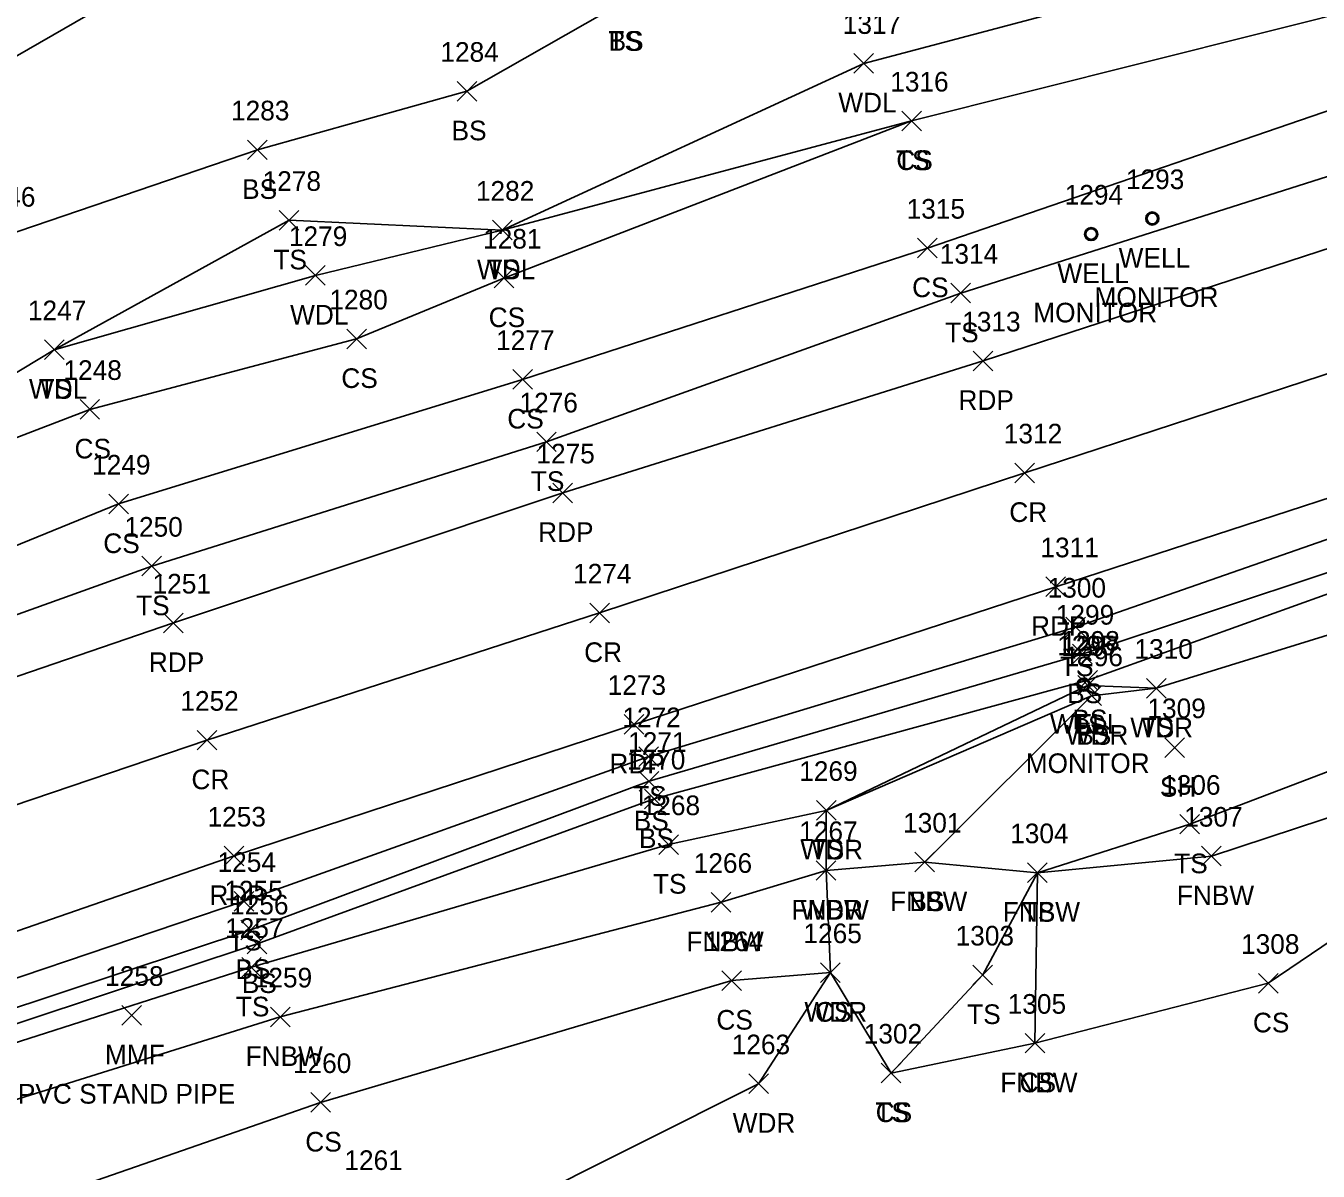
# Model space of a CAD drawing. Extents: x 1443064 to 1445163, y 544063 to 544655.
# Drawn here: x 1443463.7 to 1443595.4, y 544191.5 to 544308.2 of the extents above; entities that cross this region are included whole.
import ezdxf

# ---------------------------------------------------------------- set-up
doc = ezdxf.new("R2010")
doc.units = 0
for name, color, linetype in [('L_A', 7, 'Continuous'), ('L_C', 7, 'Continuous'), ('L_I', 7, 'Continuous'), ('L_TIC', 7, 'Continuous'), ('LAWA', 7, 'Continuous'), ('LELB', 7, 'Continuous'), ('LFNC', 7, 'Continuous'), ('P_A', 7, 'Continuous'), ('P_I', 7, 'Continuous'), ('P_TIC', 7, 'Continuous'), ('PET', 7, 'Continuous'), ('PRC', 7, 'Continuous'), ('U_A', 7, 'Continuous'), ('U_C', 7, 'Continuous'), ('U_I', 7, 'Continuous'), ('UWW', 7, 'Continuous')]:
    doc.layers.add(name, color=color, linetype=linetype)

msp = doc.modelspace()

# ---------------------------------------------------------------- linework, layer by layer
at = {"layer": 'L_TIC'}
for points in [[(1443548.07, 544303.36), (1443550.07, 544305.36)], [(1443550.07, 544303.36), (1443548.07, 544305.36)], [(1443507.64, 544300.52), (1443509.64, 544302.52)], [(1443509.64, 544300.52), (1443507.64, 544302.52)], [(1443552.95, 544297.49), (1443554.95, 544299.49)], [(1443554.95, 544297.49), (1443552.95, 544299.49)], [(1443552.95, 544297.49), (1443554.95, 544299.49)], [(1443554.95, 544297.49), (1443552.95, 544299.49)], [(1443486.3, 544294.55), (1443488.3, 544296.55)], [(1443488.3, 544294.55), (1443486.3, 544296.55)], [(1443489.52, 544287.37), (1443491.52, 544289.37)], [(1443491.52, 544287.37), (1443489.52, 544289.37)], [(1443511.25, 544286.37), (1443513.25, 544288.37)], [(1443513.25, 544286.37), (1443511.25, 544288.37)], [(1443511.25, 544286.37), (1443513.25, 544288.37)], [(1443513.25, 544286.37), (1443511.25, 544288.37)], [(1443554.56, 544284.54), (1443556.56, 544286.54)], [(1443556.56, 544284.54), (1443554.56, 544286.54)], [(1443492.21, 544281.75), (1443494.21, 544283.75)], [(1443494.21, 544281.75), (1443492.21, 544283.75)], [(1443511.42, 544281.49), (1443513.42, 544283.49)], [(1443513.42, 544281.49), (1443511.42, 544283.49)], [(1443557.95, 544279.95), (1443559.95, 544281.95)], [(1443559.95, 544279.95), (1443557.95, 544281.95)], [(1443465.61, 544274.19), (1443467.61, 544276.19)], [(1443467.61, 544274.19), (1443465.61, 544276.19)], [(1443465.61, 544274.19), (1443467.61, 544276.19)], [(1443467.61, 544274.19), (1443465.61, 544276.19)], [(1443496.41, 544275.29), (1443498.41, 544277.29)], [(1443498.41, 544275.29), (1443496.41, 544277.29)], [(1443513.32, 544271.16), (1443515.32, 544273.16)], [(1443515.32, 544271.16), (1443513.32, 544273.16)], [(1443469.23, 544268.11), (1443471.23, 544270.11)], [(1443471.23, 544268.11), (1443469.23, 544270.11)], [(1443515.75, 544264.8), (1443517.75, 544266.8)], [(1443517.75, 544264.8), (1443515.75, 544266.8)], [(1443472.16, 544258.47), (1443474.16, 544260.47)], [(1443474.16, 544258.47), (1443472.16, 544260.47)], [(1443475.53, 544252.14), (1443477.53, 544254.14)], [(1443477.53, 544252.14), (1443475.53, 544254.14)], [(1443569.65, 544245.93), (1443571.65, 544247.93)], [(1443571.65, 544245.93), (1443569.65, 544247.93)], [(1443570.34, 544243.18), (1443572.34, 544245.18)], [(1443572.34, 544243.18), (1443570.34, 544245.18)], [(1443570.88, 544239.98), (1443572.88, 544241.98)], [(1443572.88, 544239.98), (1443570.88, 544241.98)], [(1443570.89, 544240.52), (1443572.89, 544242.52)], [(1443572.89, 544240.52), (1443570.89, 544242.52)], [(1443571.28, 544238.94), (1443573.28, 544240.94)], [(1443573.28, 544238.94), (1443571.28, 544240.94)], [(1443571.28, 544238.94), (1443573.28, 544240.94)], [(1443573.28, 544238.94), (1443571.28, 544240.94)], [(1443577.87, 544239.7), (1443579.87, 544241.7)], [(1443579.87, 544239.7), (1443577.87, 544241.7)], [(1443577.87, 544239.7), (1443579.87, 544241.7)], [(1443579.87, 544239.7), (1443577.87, 544241.7)], [(1443579.75, 544233.65), (1443581.75, 544235.65)], [(1443581.75, 544233.65), (1443579.75, 544235.65)], [(1443526.17, 544232.73), (1443528.17, 544234.73)], [(1443528.17, 544232.73), (1443526.17, 544234.73)], [(1443526.2, 544230.22), (1443528.2, 544232.22)], [(1443528.2, 544230.22), (1443526.2, 544232.22)], [(1443526.73, 544228.42), (1443528.73, 544230.42)], [(1443528.73, 544228.42), (1443526.73, 544230.42)], [(1443544.25, 544227.26), (1443546.25, 544229.26)], [(1443546.25, 544227.26), (1443544.25, 544229.26)], [(1443544.25, 544227.26), (1443546.25, 544229.26)], [(1443546.25, 544227.26), (1443544.25, 544229.26)], [(1443581.29, 544225.85), (1443583.29, 544227.85)], [(1443583.29, 544225.85), (1443581.29, 544227.85)], [(1443528.19, 544223.77), (1443530.19, 544225.77)], [(1443530.19, 544223.77), (1443528.19, 544225.77)], [(1443554.28, 544221.99), (1443556.28, 544223.99)], [(1443556.28, 544221.99), (1443554.28, 544223.99)], [(1443554.28, 544221.99), (1443556.28, 544223.99)], [(1443556.28, 544221.99), (1443554.28, 544223.99)], [(1443583.49, 544222.6), (1443585.49, 544224.6)], [(1443585.49, 544222.6), (1443583.49, 544224.6)], [(1443544.24, 544221.13), (1443546.24, 544223.13)], [(1443546.24, 544221.13), (1443544.24, 544223.13)], [(1443544.24, 544221.13), (1443546.24, 544223.13)], [(1443546.24, 544221.13), (1443544.24, 544223.13)], [(1443565.76, 544220.91), (1443567.76, 544222.91)], [(1443567.76, 544220.91), (1443565.76, 544222.91)], [(1443565.76, 544220.91), (1443567.76, 544222.91)], [(1443567.76, 544220.91), (1443565.76, 544222.91)], [(1443565.76, 544220.91), (1443567.76, 544222.91)], [(1443567.76, 544220.91), (1443565.76, 544222.91)], [(1443484.93, 544217.99), (1443486.93, 544219.99)], [(1443486.93, 544217.99), (1443484.93, 544219.99)], [(1443533.54, 544217.89), (1443535.54, 544219.89)], [(1443535.54, 544217.89), (1443533.54, 544219.89)], [(1443485.62, 544215.08), (1443487.62, 544217.08)], [(1443487.62, 544215.08), (1443485.62, 544217.08)], [(1443486.26, 544213.65), (1443488.26, 544215.65)], [(1443488.26, 544213.65), (1443486.26, 544215.65)], [(1443485.7, 544211.27), (1443487.7, 544213.27)], [(1443487.7, 544211.27), (1443485.7, 544213.27)], [(1443534.62, 544209.92), (1443536.62, 544211.92)], [(1443536.62, 544209.92), (1443534.62, 544211.92)], [(1443544.67, 544210.73), (1443546.67, 544212.73)], [(1443546.67, 544210.73), (1443544.67, 544212.73)], [(1443544.67, 544210.73), (1443546.67, 544212.73)], [(1443546.67, 544210.73), (1443544.67, 544212.73)], [(1443560.2, 544210.49), (1443562.2, 544212.49)], [(1443562.2, 544210.49), (1443560.2, 544212.49)], [(1443589.28, 544209.64), (1443591.28, 544211.64)], [(1443591.28, 544209.64), (1443589.28, 544211.64)], [(1443473.49, 544206.38), (1443475.49, 544208.38)], [(1443475.49, 544206.38), (1443473.49, 544208.38)], [(1443488.63, 544206.22), (1443490.63, 544208.22)], [(1443490.63, 544206.22), (1443488.63, 544208.22)], [(1443565.51, 544203.54), (1443567.51, 544205.54)], [(1443567.51, 544203.54), (1443565.51, 544205.54)], [(1443565.51, 544203.54), (1443567.51, 544205.54)], [(1443567.51, 544203.54), (1443565.51, 544205.54)], [(1443550.85, 544200.5), (1443552.85, 544202.5)], [(1443552.85, 544200.5), (1443550.85, 544202.5)], [(1443550.85, 544200.5), (1443552.85, 544202.5)], [(1443552.85, 544200.5), (1443550.85, 544202.5)], [(1443537.36, 544199.41), (1443539.36, 544201.41)], [(1443539.36, 544199.41), (1443537.36, 544201.41)], [(1443492.74, 544197.5), (1443494.74, 544199.5)], [(1443494.74, 544197.5), (1443492.74, 544199.5)]]:
    msp.add_lwpolyline(points, dxfattribs=at)
at = {"layer": 'LAWA'}
for points in [[(1443161.29, 544157.23), (1443186.09, 544163.69), (1443194.34, 544166.63), (1443196.33, 544167.63), (1443201.36, 544168), (1443240.97, 544179.17), (1443262.42, 544188.86), (1443303.08, 544207.19), (1443347.02, 544222.79), (1443391.79, 544240.14), (1443432.68, 544254.71), (1443466.61, 544275.19), (1443493.21, 544282.75), (1443512.25, 544287.37), (1443549.07, 544304.36), (1443598.9, 544317.54), (1443643.36, 544329.59), (1443677.18, 544341.83), (1443688.03, 544341.71), (1443709.45, 544338.47), (1443741.32, 544354.61), (1443794.32, 544372.46), (1443818.98, 544380.86)], [(1443500.75, 544181.56), (1443538.36, 544200.41), (1443545.67, 544211.73), (1443545.24, 544222.13), (1443545.25, 544228.26), (1443572.28, 544239.94), (1443578.87, 544240.7), (1443627.04, 544255.63), (1443659.19, 544265.88), (1443688.01, 544274.03), (1443699.53, 544278.63), (1443728.36, 544290.25)]]:
    msp.add_lwpolyline(points, dxfattribs=at)
at = {"layer": 'LELB'}
for points in [[(1443073.59, 544128.34), (1443116.66, 544141.89), (1443162.8, 544149.75), (1443198.07, 544157.24), (1443242.5, 544173.41), (1443262.84, 544182.05), (1443307.11, 544199.46), (1443348.85, 544214.35), (1443394.74, 544233.02), (1443435.02, 544243.93), (1443473.16, 544259.47), (1443514.32, 544272.16), (1443555.56, 544285.54), (1443605.06, 544302.52), (1443644.56, 544313.72), (1443676.09, 544324.26), (1443689.45, 544326.75), (1443708.55, 544330.01), (1443714.07, 544333.45), (1443742.84, 544349.83), (1443793.92, 544368.99), (1443822.61, 544377.56)], [(1443074.67, 544122.4), (1443120.32, 544131.74), (1443165.11, 544143.77), (1443199.58, 544153.13), (1443245.24, 544167.88), (1443264.59, 544177.57), (1443308.86, 544194.48), (1443350.56, 544209.36), (1443397.32, 544225.82), (1443437.1, 544238.98), (1443476.53, 544253.14), (1443516.75, 544265.8), (1443558.95, 544280.95), (1443607.52, 544296.39), (1443646.45, 544306.32), (1443685.12, 544319.06), (1443714.26, 544329.16), (1443721.31, 544331.26), (1443744.28, 544345.57), (1443795.65, 544366.53), (1443822.61, 544377.56)], [(1443298.3, 544219.12), (1443343.36, 544234.64), (1443347.13, 544235.69), (1443361.65, 544240.04), (1443373.89, 544246.37), (1443387.28, 544254.4), (1443426.15, 544267.88), (1443461.49, 544286.76), (1443487.3, 544295.55), (1443508.64, 544301.52), (1443524.64, 544310.64), (1443543.83, 544318.46), (1443565.18, 544320.82), (1443579.86, 544324.28), (1443590.71, 544328.22), (1443606.37, 544329.69), (1443641.44, 544343.33), (1443674.4, 544354.73), (1443679.77, 544354.99), (1443682.99, 544355.5), (1443689.34, 544351.28), (1443707.83, 544344.95), (1443741.32, 544354.61)], [(1443361.65, 544240.04), (1443365.6, 544252.15), (1443382.87, 544266.28), (1443423.93, 544281.08), (1443455.64, 544301.02), (1443483.09, 544316.84), (1443502.95, 544323.75), (1443492.91, 544341.29), (1443492.61, 544354.67)], [(1443082.68, 544086.51), (1443130.13, 544099.67), (1443144.13, 544104.98), (1443172.72, 544113.76), (1443212.83, 544125.42), (1443253.97, 544138.87), (1443319.39, 544160.76), (1443361, 544176.06), (1443409.52, 544193.8), (1443447.54, 544206.03), (1443485.93, 544218.99), (1443527.17, 544233.73), (1443570.65, 544246.93), (1443621.44, 544264.66), (1443656.15, 544276.08), (1443695.78, 544288.38), (1443720.36, 544296.79), (1443749.28, 544306.83), (1443759.63, 544310.57), (1443806.78, 544328.14), (1443835.8, 544338.24)], [(1443466.61, 544275.19), (1443490.52, 544288.37), (1443512.25, 544287.37), (1443553.95, 544298.49), (1443601.6, 544310.47), (1443642.31, 544323.29), (1443675.99, 544336.7), (1443688, 544336.24), (1443698.55, 544337.96), (1443699.43, 544334.12), (1443708.55, 544330.01)], [(1443319.92, 544153.98), (1443361.38, 544174.3), (1443410.41, 544191.66), (1443447.48, 544203.1), (1443486.62, 544216.08), (1443527.2, 544231.22), (1443571.34, 544244.18), (1443622.82, 544261.27), (1443656.98, 544272.97), (1443695.69, 544285.56), (1443722.38, 544294.2), (1443748.12, 544301.75), (1443761.69, 544309.21), (1443807.82, 544325.32), (1443837.04, 544335.82)], [(1443432.68, 544254.71), (1443470.23, 544269.11), (1443497.41, 544276.29), (1443512.42, 544282.49), (1443553.95, 544298.49)], [(1443347.34, 544164.94), (1443362.1, 544171.53), (1443410.79, 544190.32), (1443447.84, 544201.59), (1443487.26, 544214.65), (1443527.73, 544229.42), (1443571.89, 544241.52), (1443623.27, 544260), (1443657.62, 544270.44), (1443688.01, 544274.03), (1443701.05, 544275.03), (1443736.1, 544284.41), (1443746.14, 544291.27)], [(1443551.85, 544201.5), (1443561.2, 544211.49), (1443566.76, 544221.91), (1443582.29, 544226.85), (1443631, 544245.39), (1443663.73, 544256.35), (1443704.83, 544270.63), (1443733.57, 544280.99), (1443742.56, 544273.31)], [(1443347.34, 544164.94), (1443362.66, 544168.7), (1443411.3, 544188.87), (1443447.45, 544199.71), (1443486.7, 544212.27), (1443529.19, 544224.77), (1443545.25, 544228.26), (1443571.88, 544240.98), (1443578.87, 544240.7)], [(1443326.71, 544136.88), (1443356.07, 544155.13), (1443385.8, 544161.03), (1443414.14, 544171.77), (1443454.43, 544184.84), (1443493.74, 544198.5), (1443535.62, 544210.92), (1443545.67, 544211.73), (1443551.85, 544201.5), (1443566.51, 544204.54), (1443590.28, 544210.64), (1443632.95, 544239.56)], [(1443572.28, 544239.94), (1443555.28, 544222.99)]]:
    msp.add_lwpolyline(points, dxfattribs=at)
at = {"layer": 'LFNC'}
for points in [[(1443239.88, 544119.45), (1443278.62, 544130.94), (1443320.57, 544148.06), (1443338.13, 544157.08), (1443351.22, 544161.82), (1443363.5, 544166.21), (1443412.24, 544182.91), (1443449.91, 544194.79), (1443489.63, 544207.22), (1443534.54, 544218.89), (1443545.24, 544222.13), (1443555.28, 544222.99), (1443566.76, 544221.91), (1443584.49, 544223.6), (1443632.95, 544239.56), (1443668.35, 544248.03), (1443707.08, 544263.81), (1443742.56, 544273.31)], [(1443566.76, 544221.91), (1443566.51, 544204.54)]]:
    msp.add_lwpolyline(points, dxfattribs=at)
at = {"layer": 'P_TIC'}
for points in [[(1443560.23, 544273.05), (1443562.23, 544275.05)], [(1443562.23, 544273.05), (1443560.23, 544275.05)], [(1443564.47, 544261.64), (1443566.47, 544263.64)], [(1443566.47, 544261.64), (1443564.47, 544263.64)], [(1443517.41, 544259.6), (1443519.41, 544261.6)], [(1443519.41, 544259.6), (1443517.41, 544261.6)], [(1443567.63, 544250.04), (1443569.63, 544252.04)], [(1443569.63, 544250.04), (1443567.63, 544252.04)], [(1443521.16, 544247.37), (1443523.16, 544249.37)], [(1443523.16, 544247.37), (1443521.16, 544249.37)], [(1443477.75, 544246.35), (1443479.75, 544248.35)], [(1443479.75, 544246.35), (1443477.75, 544248.35)], [(1443524.67, 544236.02), (1443526.67, 544238.02)], [(1443526.67, 544236.02), (1443524.67, 544238.02)], [(1443481.15, 544234.41), (1443483.15, 544236.41)], [(1443483.15, 544234.41), (1443481.15, 544236.41)], [(1443483.92, 544222.61), (1443485.92, 544224.61)], [(1443485.92, 544222.61), (1443483.92, 544224.61)]]:
    msp.add_lwpolyline(points, dxfattribs=at)
at = {"layer": 'PET'}
for points in [[(1443075.39, 544117.71), (1443121.41, 544129.24), (1443165.99, 544140.07), (1443200.71, 544149.88), (1443246.42, 544165.39), (1443265.96, 544172.48), (1443311.2, 544187.88), (1443352.92, 544202.76), (1443399.28, 544220.13), (1443438.78, 544233.67), (1443478.75, 544247.35), (1443518.41, 544260.6), (1443561.23, 544274.05), (1443611.7, 544290.5), (1443646.84, 544301.68), (1443684.98, 544314.55), (1443724.57, 544327.54), (1443735.41, 544331.22), (1443748.81, 544336.36), (1443799.43, 544353.96), (1443827.31, 544364.14)], [(1443081.93, 544089.54), (1443128.67, 544104.01), (1443173.03, 544117.15), (1443209.23, 544128.71), (1443253.49, 544142.88), (1443273.3, 544149.07), (1443318.27, 544165.2), (1443359.78, 544179.84), (1443408.54, 544196.96), (1443445.92, 544210.12), (1443484.92, 544223.61), (1443525.67, 544237.02), (1443568.63, 544251.04), (1443620.57, 544267.93), (1443654.52, 544278.93), (1443694.69, 544292.43), (1443717.24, 544299.44), (1443752.8, 544310.97), (1443757.72, 544314.31), (1443805.74, 544330.07), (1443835.35, 544341.18)]]:
    msp.add_lwpolyline(points, dxfattribs=at)
at = {"layer": 'PRC'}
msp.add_lwpolyline([(1443078.47, 544103.68), (1443125.02, 544115.93), (1443169.41, 544128.22), (1443204.47, 544139.4), (1443250.36, 544154.3), (1443269.99, 544160.83), (1443315.13, 544176.71), (1443356.58, 544191.19), (1443403.59, 544208.05), (1443442.67, 544222.02), (1443482.15, 544235.41), (1443522.16, 544248.37), (1443565.47, 544262.64), (1443616.51, 544279.34), (1443650.9, 544289.93), (1443689.58, 544302.53), (1443728.44, 544315.77), (1443753.53, 544324.68), (1443803.56, 544342.2), (1443830.96, 544352.16)], dxfattribs=at)
at = {"layer": 'UWW'}
for centre, radius in [((1443578.47, 544288.55), 0.667), ((1443578.47, 544288.55), 0.625), ((1443578.47, 544288.55), 0.583), ((1443578.47, 544288.55), 0.542), ((1443572.24, 544286.97), 0.667), ((1443572.24, 544286.97), 0.625), ((1443572.24, 544286.97), 0.583), ((1443572.24, 544286.97), 0.542), ((1443571.47, 544241.06), 0.667), ((1443571.47, 544241.06), 0.625), ((1443571.47, 544241.06), 0.583), ((1443571.47, 544241.06), 0.542)]:
    msp.add_circle(centre, radius, dxfattribs=at)

# ---------------------------------------------------------------- texts
at = {"layer": 'L_A'}
for s, p in [('TS', (1443523.05, 544305.64)), ('BS', (1443523.08, 544305.64)), ('BS', (1443523.08, 544305.64)), ('WDL', (1443546.48, 544299.36)), ('BS', (1443507.08, 544296.52)), ('TS', (1443552.36, 544293.49)), ('CS', (1443552.39, 544293.49)), ('BS', (1443485.74, 544290.55)), ('TS', (1443488.93, 544283.37)), ('WDL', (1443509.67, 544282.37)), ('TS', (1443510.66, 544282.37)), ('CS', (1443554, 544280.54)), ('WDL', (1443490.63, 544277.75)), ('CS', (1443510.86, 544277.49)), ('TS', (1443557.36, 544275.95)), ('WDL', (1443464.03, 544270.19)), ('TS', (1443465.02, 544270.19)), ('CS', (1443495.85, 544271.29)), ('CS', (1443512.76, 544267.16)), ('CS', (1443468.67, 544264.11)), ('TS', (1443515.16, 544260.8)), ('CS', (1443471.6, 544254.47)), ('TS', (1443474.94, 544248.14)), ('TS', (1443569.06, 544241.93)), ('BS', (1443569.79, 544239.18)), ('TS', (1443570.29, 544235.98)), ('BS', (1443570.33, 544236.52)), ('WDR', (1443569.64, 544234.94)), ('BS', (1443570.72, 544234.94)), ('WDR', (1443576.23, 544235.7)), ('TS', (1443577.28, 544235.7)), ('SH', (1443579.24, 544229.65)), ('TS', (1443525.58, 544228.73)), ('BS', (1443525.64, 544226.22)), ('BS', (1443526.17, 544224.42)), ('WDR', (1443542.61, 544223.26)), ('TS', (1443543.66, 544223.26)), ('TS', (1443580.7, 544221.85)), ('TS', (1443527.6, 544219.77)), ('FNBW', (1443551.75, 544217.99)), ('BS', (1443553.72, 544217.99)), ('FNBW', (1443580.97, 544218.6)), ('FNBW', (1443541.71, 544217.13)), ('WDR', (1443542.6, 544217.13)), ('FNBW', (1443563.23, 544216.91)), ('FNBW', (1443563.23, 544216.91)), ('TS', (1443565.17, 544216.91)), ('TS', (1443484.34, 544213.99)), ('FNBW', (1443531.01, 544213.89)), ('BS', (1443485.06, 544211.08)), ('BS', (1443485.71, 544209.65)), ('TS', (1443485.11, 544207.27)), ('CS', (1443534.06, 544205.92)), ('WDR', (1443543.03, 544206.73)), ('CS', (1443544.11, 544206.73)), ('TS', (1443559.61, 544206.49)), ('CS', (1443588.72, 544205.64)), ('MMF', (1443471.77, 544202.38)), ('FNBW', (1443486.1, 544202.22)), ('FNBW', (1443562.98, 544199.54)), ('CS', (1443564.95, 544199.54)), ('TS', (1443550.26, 544196.5)), ('CS', (1443550.29, 544196.5)), ('WDR', (1443535.72, 544195.41)), ('CS', (1443492.18, 544193.5))]:
    msp.add_text(s, height=2, dxfattribs=at).set_placement(p)
at = {"layer": 'L_C'}
msp.add_text(' 2"PVC STAND PIPE', height=2, dxfattribs=at).set_placement((1443459.72, 544198.38))
at = {"layer": 'L_I'}
for s, p in [('1317', (1443546.94, 544307.36)), ('1284', (1443505.94, 544304.52)), ('1316', (1443551.77, 544301.49)), ('1316', (1443551.77, 544301.49)), ('1283', (1443484.61, 544298.55)), ('1278', (1443487.83, 544291.37)), ('1282', (1443509.56, 544290.37)), ('1282', (1443509.56, 544290.37)), ('1246', (1443458.74, 544289.76)), ('1315', (1443553.44, 544288.54)), ('1279', (1443490.51, 544285.75)), ('1281', (1443510.29, 544285.49)), ('1314', (1443556.82, 544283.95)), ('1247', (1443463.92, 544278.19)), ('1247', (1443463.92, 544278.19)), ('1280', (1443494.63, 544279.29)), ('1277', (1443511.62, 544275.16)), ('1248', (1443467.54, 544272.11)), ('1276', (1443514, 544268.8)), ('1249', (1443470.46, 544262.47)), ('1250', (1443473.75, 544256.14)), ('1300', (1443567.8, 544249.93)), ('1299', (1443568.64, 544247.18)), ('1297', (1443569.19, 544243.98)), ('1298', (1443569.2, 544244.52)), ('1296', (1443569.53, 544242.94)), ('1296', (1443569.53, 544242.94)), ('1310', (1443576.65, 544243.7)), ('1310', (1443576.65, 544243.7)), ('1309', (1443577.97, 544237.65)), ('1272', (1443524.48, 544236.73)), ('1271', (1443525.07, 544234.22)), ('1270', (1443524.95, 544232.42)), ('1269', (1443542.5, 544231.26)), ('1269', (1443542.5, 544231.26)), ('1306', (1443579.47, 544229.85)), ('1268', (1443526.45, 544227.77)), ('1301', (1443553.08, 544225.99)), ('1301', (1443553.08, 544225.99)), ('1307', (1443581.72, 544226.6)), ('1267', (1443542.5, 544225.13)), ('1267', (1443542.5, 544225.13)), ('1304', (1443563.99, 544224.91)), ('1304', (1443563.99, 544224.91)), ('1304', (1443563.99, 544224.91)), ('1254', (1443483.24, 544221.99)), ('1266', (1443531.75, 544221.89)), ('1255', (1443483.93, 544219.08)), ('1256', (1443484.52, 544217.65)), ('1257', (1443484.01, 544215.27)), ('1264', (1443532.88, 544213.92)), ('1265', (1443542.93, 544214.73)), ('1265', (1443542.93, 544214.73)), ('1303', (1443558.43, 544214.49)), ('1308', (1443587.51, 544213.64)), ('1258', (1443471.79, 544210.38)), ('1259', (1443486.93, 544210.22)), ('1305', (1443563.74, 544207.54)), ('1305', (1443563.74, 544207.54)), ('1302', (1443549.07, 544204.5)), ('1302', (1443549.07, 544204.5)), ('1263', (1443535.62, 544203.41)), ('1260', (1443490.92, 544201.5)), ('1261', (1443496.16, 544191.62))]:
    msp.add_text(s, height=2, dxfattribs=at).set_placement(p)
at = {"layer": 'P_A'}
for s, p in [('RDP', (1443558.72, 544269.05)), ('CR', (1443563.9, 544257.64)), ('RDP', (1443515.9, 544255.6)), ('RDP', (1443566.12, 544246.04)), ('CR', (1443520.59, 544243.37)), ('RDP', (1443476.24, 544242.35)), ('RDP', (1443523.16, 544232.02)), ('CR', (1443480.58, 544230.41)), ('RDP', (1443482.41, 544218.61))]:
    msp.add_text(s, height=2, dxfattribs=at).set_placement(p)
at = {"layer": 'P_I'}
for s, p in [('1313', (1443559.1, 544277.05)), ('1312', (1443563.34, 544265.64)), ('1275', (1443515.72, 544263.6)), ('1311', (1443567.07, 544254.04)), ('1274', (1443519.46, 544251.37)), ('1251', (1443476.62, 544250.35)), ('1273', (1443522.98, 544240.02)), ('1252', (1443479.45, 544238.41)), ('1253', (1443482.22, 544226.61))]:
    msp.add_text(s, height=2, dxfattribs=at).set_placement(p)
at = {"layer": 'U_A'}
for p in [(1443575.04, 544283.55), (1443568.8, 544281.97), (1443568.04, 544236.06)]:
    msp.add_text('WELL', height=2, dxfattribs=at).set_placement(p)
at = {"layer": 'U_C'}
for p in [(1443572.58, 544279.55), (1443566.34, 544277.97), (1443565.57, 544232.06)]:
    msp.add_text('MONITOR', height=2, dxfattribs=at).set_placement(p)
at = {"layer": 'U_I'}
for s, p in [('1293', (1443575.78, 544291.55)), ('1294', (1443569.54, 544289.97)), ('1295', (1443568.78, 544244.06))]:
    msp.add_text(s, height=2, dxfattribs=at).set_placement(p)

doc.saveas('drawing.dxf')
